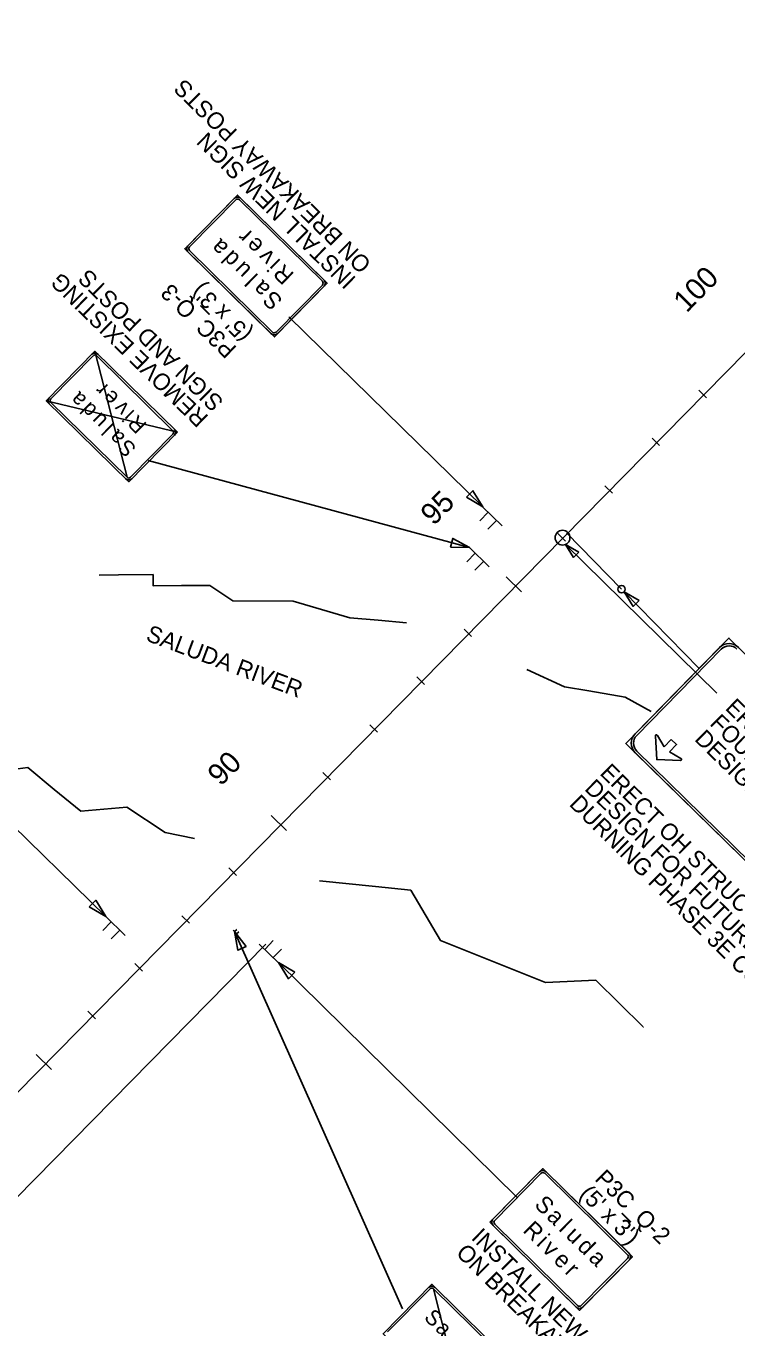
# Model space of a CAD drawing. Extents: x -5665 to 1997148, y 4 to 812485.
# Drawn here: x 1960598 to 1961659, y 796785 to 798728 of the extents above; entities that cross this region are included whole.
import ezdxf

# ---------------------------------------------------------------- set-up
doc = ezdxf.new("R2010")
doc.units = 0
for name, color, linetype in [('Default', 7, 'Continuous'), ('RD_HC_CL_Rel', 7, 'Continuous'), ('RD_HC_Data_Tic_Rel', 7, 'Continuous'), ('RD_HC_TX_Rel_Sta50', 7, 'Continuous'), ('RD_PD_Final_TX', 7, 'Continuous'), ('RD_SHT_ID', 7, 'Continuous'), ('RD_SHT_TX', 7, 'Continuous'), ('TR SN EXTRUDED PANEL SIGNS- MOUNTED OVERHEAD', 7, 'Continuous'), ('TR SN UNASSIGNED 10', 7, 'Continuous')]:
    doc.layers.add(name, color=color, linetype=linetype)

msp = doc.modelspace()

# ---------------------------------------------------------------- linework, layer by layer
at = {"layer": 'Default'}
msp.add_line((1960426.3, 796819.7), (1960955.8, 797357.9), dxfattribs=at)
at = {"layer": 'RD_HC_CL_Rel'}
msp.add_line((1957622, 794124.4), (1963740.1, 800343.8), dxfattribs=at)
at = {"layer": 'RD_HC_Data_Tic_Rel'}
for p, q in [((1961613.4, 798173.3), (1961602, 798184.6)), ((1961543.3, 798102), (1961531.9, 798113.3)), ((1961473.2, 798030.8), (1961461.7, 798042)), ((1961403, 797959.5), (1961391.6, 797970.7)), ((1961337.2, 797884), (1961314.4, 797906.4)), ((1961262.8, 797816.9), (1961251.4, 797828.1)), ((1961192.6, 797745.6), (1961181.2, 797756.8)), ((1961122.5, 797674.3), (1961111.1, 797685.5)), ((1961052.4, 797603), (1961041, 797614.2)), ((1960986.5, 797527.5), (1960963.7, 797550)), ((1960912.1, 797460.4), (1960900.7, 797471.7)), ((1960842, 797389.2), (1960830.6, 797400.4)), ((1960771.9, 797317.9), (1960760.5, 797329.1)), ((1960701.8, 797246.6), (1960690.3, 797257.8)), ((1960635.9, 797171.1), (1960613.1, 797193.5))]:
    msp.add_line(p, q, dxfattribs=at)
at = {"layer": 'RD_PD_Final_TX'}
for points in [[(1961255, 798024.9), (1961264.6, 798034.7), (1961279.5, 798010.4)], [(1961231, 797950.4), (1961234.6, 797963.6), (1961259.4, 797949.8)], [(1961422.6, 797943), (1961414.9, 797935.2), (1961403, 797954.6)], [(1960692.3, 797413.8), (1960701.9, 797423.6), (1960716.8, 797399.4)], [(1960926.6, 797354.6), (1960914.1, 797349), (1960909.2, 797377)], [(1960999.1, 797316.1), (1960989.4, 797306.3), (1960974.6, 797330.5)]]:
    msp.add_lwpolyline(points, close=True, dxfattribs=at)
at = {"layer": 'RD_SHT_ID'}
for points in [[(1961165.7, 797837.4), (1961123.4, 797841.3), (1961081.1, 797845.2), (1960996.3, 797869.9), (1960906.4, 797870.3), (1960872.3, 797893.3), (1960830, 797893), (1960787.7, 797892.6), (1960787.6, 797909.5), (1960735.8, 797909.1), (1960707.2, 797908.9)], [(1961345.1, 797768), (1961401.3, 797742), (1961401.3, 797742), (1961437.4, 797736), (1961492, 797726.8), (1961530.7, 797705)], [(1960849.1, 797515.5), (1960805.7, 797524.7), (1960748.2, 797562.3), (1960748.2, 797562.3), (1960679.5, 797556.5), (1960640.1, 797589), (1960600.7, 797621.5), (1960555.3, 797615.8), (1960534.7, 797613.2), (1960515.9, 797641.9), (1960503.2, 797633.6), (1960494.9, 797646.3), (1960494.9, 797646.3)], [(1961035.8, 797452.7), (1961119.1, 797444.1), (1961172, 797438.7), (1961216.1, 797363.5), (1961347.9, 797310.8), (1961373, 797300.8), (1961447.9, 797304.2), (1961483.4, 797269.4), (1961518.8, 797234.5), (1961518.8, 797234.5), (1961518.8, 797234.5)]]:
    msp.add_lwpolyline(points, dxfattribs=at)
at = {"layer": 'TR SN EXTRUDED PANEL SIGNS- MOUNTED OVERHEAD'}
for p, q in [((1960990, 798294.4), (1961279.5, 798010.4)), ((1960700.8, 798242.8), (1960748.6, 798054.7)), ((1960628.2, 798169), (1960823.8, 798121.9)), ((1960780.2, 798079.9), (1961259.4, 797949.8)), ((1961274.9, 797989.8), (1961287.2, 798002.6)), ((1961308.2, 797982.3), (1961278.7, 798010.9)), ((1961287.1, 797977.1), (1961299.5, 797989.9)), ((1961288.9, 797921.2), (1961259.4, 797949.8)), ((1961403, 797954.6), (1961628.8, 797732.5)), ((1961255.5, 797928.7), (1961267.9, 797941.5)), ((1961267.7, 797916), (1961280.1, 797928.8)), ((1960716.8, 797399.4), (1960410.5, 797698.9)), ((1960746, 797371.1), (1960716.5, 797399.6)), ((1960712.7, 797378.5), (1960725, 797391.3)), ((1960724.9, 797365.8), (1960737.3, 797378.6)), ((1960907, 797378.7), (1960914.1, 797371.3)), ((1960912.4, 797379.8), (1960909.2, 797376.7)), ((1961159.6, 796813.7), (1960909.2, 797377)), ((1960915.3, 797376.5), (1960912.1, 797373.4)), ((1960966.9, 797363.4), (1960954.5, 797350.6)), ((1960945.7, 797358.2), (1960975.3, 797329.7)), ((1960979.1, 797350.7), (1960966.7, 797337.9)), ((1960974.6, 797330.5), (1961330.9, 796980)), ((1961253.7, 796655.6), (1961205.9, 796843.8))]:
    msp.add_line(p, q, dxfattribs=at)
for points in [[(1961047.3, 798344.5), (1960913.6, 798476), (1960834.7, 798395.8), (1960968.4, 798264.3), (1961047.3, 798344.5), (1961047.3, 798344.5), (1961047.3, 798344.5)], [(1960839.7, 798400.8), (1960908.7, 798471)], [(1960910.9, 798468.8), (1960841.9, 798398.6)], [(1960910.9, 798468.8), (1960910.9, 798468.8), (1960910.9, 798468.8)], [(1961040.1, 798347.2), (1960916.4, 798468.8)], [(1960918.6, 798471), (1961042.3, 798349.4)], [(1960963.4, 798269.2), (1960839.7, 798390.8)], [(1960841.9, 798393.1), (1960965.6, 798271.4)], [(1960841.9, 798393.1), (1960841.9, 798393.1), (1960841.9, 798393.1)], [(1960971.1, 798271.5), (1961040.1, 798341.7)], [(1961042.4, 798339.5), (1960973.3, 798269.3)], [(1961040.1, 798347.2), (1961040.1, 798347.2), (1961040.1, 798347.2)], [(1960971.1, 798271.5), (1960971.1, 798271.5), (1960971.1, 798271.5)], [(1960823.8, 798121.9), (1960700.8, 798242.8), (1960628.2, 798169), (1960751.2, 798048.1), (1960823.8, 798121.9), (1960823.8, 798121.9), (1960823.8, 798121.9)], [(1960698.3, 798236.2), (1960634.8, 798171.6)], [(1960698.3, 798236.2), (1960698.3, 798236.2), (1960698.3, 798236.2)], [(1960817.1, 798124.3), (1960703.4, 798236.2)], [(1960634.8, 798166.6), (1960748.6, 798054.7)], [(1960634.8, 798166.6), (1960634.8, 798166.6), (1960634.8, 798166.6)], [(1960753.7, 798054.7), (1960817.2, 798119.3)], [(1960817.1, 798124.3), (1960817.1, 798124.3), (1960817.1, 798124.3)], [(1960753.7, 798054.7), (1960753.7, 798054.7), (1960753.7, 798054.7)], [(1961290.1, 796942.9), (1961423.7, 796811.4), (1961502.6, 796891.6), (1961368.9, 797023.1), (1961290.1, 796942.9), (1961290.1, 796942.9), (1961290.1, 796942.9)], [(1961295, 796947.9), (1961364, 797018.1)], [(1961366.2, 797015.9), (1961297.2, 796945.8)], [(1961366.2, 797015.9), (1961366.2, 797015.9), (1961366.2, 797015.9)], [(1961495.4, 796894.3), (1961371.8, 797016)], [(1961374, 797018.2), (1961497.6, 796896.6)], [(1961418.7, 796816.4), (1961295.1, 796938)], [(1961297.3, 796940.2), (1961420.9, 796818.6)], [(1961297.3, 796940.2), (1961297.3, 796940.2), (1961297.3, 796940.2)], [(1961495.4, 796894.3), (1961495.4, 796894.3), (1961495.4, 796894.3)], [(1961426.4, 796818.6), (1961495.5, 796888.8)], [(1961497.7, 796886.6), (1961428.7, 796816.5)], [(1961130.7, 796776.6), (1961253.7, 796655.6), (1961326.3, 796729.4), (1961203.3, 796850.4), (1961130.7, 796776.6), (1961130.7, 796776.6), (1961130.7, 796776.6)], [(1961200.8, 796843.8), (1961137.3, 796779.2)], [(1961200.8, 796843.8), (1961200.8, 796843.8), (1961200.8, 796843.8)], [(1961319.6, 796731.9), (1961205.9, 796843.8)], [(1961426.4, 796818.6), (1961426.4, 796818.6), (1961426.4, 796818.6)]]:
    msp.add_lwpolyline(points, dxfattribs=at)
msp.add_circle((1961398.4, 797964.7), 11.1, dxfattribs=at)
for centre, radius, start, end in [((1960913.7, 798466), 7.03, 45.4705, 135.4707), ((1960913.7, 798466), 3.91, 45.4705, 135.4707), ((1960844.7, 798395.9), 7.03, 135.4705, 225.4707), ((1960844.7, 798395.9), 3.91, 135.4705, 225.4707), ((1961037.3, 798344.4), 3.91, 315.4703, 45.4705), ((1961037.3, 798344.4), 7.03, 315.4703, 45.4705), ((1960968.3, 798274.2), 7.03, 225.4707, 315.4703), ((1960968.3, 798274.2), 3.91, 225.4707, 315.4703), ((1960700.9, 798233.7), 6.47, 45.4705, 135.4707), ((1960700.9, 798233.7), 3.59, 45.4705, 135.4707), ((1960637.4, 798169.1), 6.47, 135.4705, 225.4707), ((1960637.4, 798169.1), 3.59, 135.4705, 225.4707), ((1960814.6, 798121.8), 3.59, 315.4703, 45.4705), ((1960814.6, 798121.8), 6.47, 315.4703, 45.4705), ((1960751.1, 798057.2), 6.47, 225.4707, 315.4703), ((1960751.1, 798057.2), 3.59, 225.4707, 315.4703), ((1961369, 797013.2), 7.03, 45.4707, 135.4703), ((1961369, 797013.2), 3.91, 45.4707, 135.4703), ((1961300, 796943), 7.03, 135.4703, 225.4705), ((1961300, 796943), 3.91, 135.4703, 225.4705), ((1961492.7, 796891.6), 3.91, 315.4705, 45.4707), ((1961492.7, 796891.6), 7.03, 315.4705, 45.4707), ((1961203.4, 796841.2), 6.47, 45.4707, 135.4703), ((1961203.4, 796841.2), 3.59, 45.4707, 135.4703), ((1961423.6, 796821.4), 3.91, 225.4705, 315.4707), ((1961423.6, 796821.4), 7.03, 225.4705, 315.4707)]:
    msp.add_arc(centre, radius, start, end, dxfattribs=at)
at = {"layer": 'TR SN UNASSIGNED 10'}
for p, q in [((1961404.4, 797971.8), (1961486.5, 797887.8)), ((1961602.2, 797769.4), (1961490.5, 797883.9)), ((1961536.9, 797668.6), (1961538.9, 797633.4)), ((1961550.2, 797652.6), (1961540, 797669.6)), ((1961560.7, 797663.3), (1961550.2, 797652.6)), ((1961538.9, 797633.4), (1961574.2, 797632.1)), ((1961575.1, 797635.2), (1961558, 797645))]:
    msp.add_line(p, q, dxfattribs=at)
msp.add_lwpolyline([(1961512.5, 797870.9), (1961503.8, 797862.1), (1961490.5, 797883.9)], close=True, dxfattribs=at)
for points in [[(1961492.7, 797657.6), (1961907, 797251.7), (1962061, 797408.8), (1961646.7, 797814.8), (1961492.7, 797657.6), (1961492.7, 797657.6)], [(1961506.7, 797671.9), (1961632.7, 797800.5)], [(1961635.1, 797798.2), (1961509.1, 797669.6)], [(1961536.9, 797668.6), (1961538.9, 797633.4), (1961538.9, 797633.4)], [(1961550.2, 797652.6), (1961540, 797669.6)], [(1961550.2, 797652.6), (1961560.7, 797663.3), (1961560.7, 797663.3)], [(1961560.7, 797663.3), (1961568.5, 797655.8), (1961558, 797645)], [(1961558, 797645), (1961568.5, 797655.8), (1961560.7, 797663.3)], [(1961892.7, 797265.7), (1961507, 797643.6)], [(1961509.3, 797646), (1961895, 797268.1)], [(1961538.9, 797633.4), (1961574.2, 797632.1)], [(1961575.1, 797635.2), (1961558, 797645)]]:
    msp.add_lwpolyline(points, dxfattribs=at)
msp.add_circle((1961486.5, 797887.8), 5.54, dxfattribs=at)
for centre, radius, start, end in [((1961647, 797786.5), 20, 45.5831, 135.5828), ((1961647, 797786.5), 16.7, 45.5831, 135.5828), ((1961521, 797657.9), 20, 135.5828, 225.583), ((1961521, 797657.9), 16.7, 135.5828, 225.583), ((1961538.6, 797668.7), 1.67, 31.1102, 182.5579), ((1961538.6, 797668.7), 1.67, 31.1102, 182.5579), ((1961574.3, 797633.7), 1.67, 268.6081, 60.0557), ((1961574.3, 797633.7), 1.67, 268.6081, 60.0557)]:
    msp.add_arc(centre, radius, start, end, dxfattribs=at)

# ---------------------------------------------------------------- texts
at = {"layer": 'RD_HC_TX_Rel_Sta50'}
for s, p in [('100', (1961583.5, 798299.2)), ('95', (1961206.2, 797981.4)), ('90', (1960888.4, 797592.6))]:
    msp.add_text(s, height=32, rotation=45.4705, dxfattribs=at).set_placement(p)
at = {"layer": 'RD_SHT_TX'}
msp.add_text('SALUDA RIVER', height=25, rotation=339.371, dxfattribs=at).set_placement((1960775.2, 797811.6))
at = {"layer": 'TR SN EXTRUDED PANEL SIGNS- MOUNTED OVERHEAD'}
for s, height, rotation, p in [('ON BREAKAWAY POSTS', 25, 135.4705, (1961114.6, 798374.6)), ('INSTALL NEW SIGN', 25, 135.4705, (1961091.8, 798351.4)), ('a', 25, 135.4705, (1960901.3, 798399.3)), ('r', 25, 135.4705, (1960936.5, 798419.5)), ('e', 25, 135.4705, (1960953.7, 798402.6)), ('d', 25, 135.4705, (1960918.4, 798382.5)), ('v', 25, 135.4705, (1960970.7, 798385.9)), ('u', 25, 135.4705, (1960935.4, 798365.8)), ('i', 25, 135.4705, (1960979, 798377.7)), ('R', 25, 135.4705, (1960999.2, 798357.8)), ('REMOVE EXISTING', 25, 135.6376, (1960871.5, 798145.2)), ('SIGN AND POSTS', 25, 135.6376, (1960894.2, 798168.5)), ('l', 25, 135.4705, (1960945.6, 798355.7)), ('P3C_Q-3', 25, 135.6376, (1960913.8, 798248.1)), ("(5' x 3')", 25, 135.6376, (1960936.6, 798271.3)), ('a', 25, 135.4705, (1960963.9, 798337.7)), ('S', 25, 135.4705, (1960982.3, 798319.6)), ('a', 23, 135.4705, (1960689.5, 798172.3)), ('r', 23, 135.4705, (1960721.9, 798190.8)), ('e', 23, 135.4705, (1960737.7, 798175.3)), ('d', 23, 135.4705, (1960705.2, 798156.9)), ('v', 23, 135.4705, (1960753.3, 798160)), ('u', 23, 135.4705, (1960720.8, 798141.4)), ('i', 23, 135.4705, (1960761, 798152.4)), ('R', 23, 135.4705, (1960779.5, 798134.1)), ('l', 23, 135.4705, (1960730.2, 798132.2)), ('a', 23, 135.4705, (1960747.1, 798115.6)), ('S', 23, 135.4705, (1960764, 798099)), ('ERECT OVERHEAD BRIDGE TYPE STRUCTURE', 25, 315.4705, (1961639.7, 797709.1)), ('FOUNDATION NO. P3C_OH-9 IN MEDIAN ONLY.', 25, 315.4705, (1961616.9, 797685.9)), ("DESIGN FUTURE BRIDGE STRUCTURE FOR SIGN SIZE 70'x 18'.", 25, 315.4705, (1961594, 797662.7)), ('P3C_Q-2', 25, 315.3323, (1961445.1, 797006.3)), ("(5' x 3')", 25, 315.3323, (1961422.2, 796983.1)), ('S', 25, 315.4705, (1961355, 796967.8)), ('a', 25, 315.4705, (1961373.4, 796949.7)), ('INSTALL NEW SIGN', 25, 315.4705, (1961260.9, 796918.7)), ('R', 25, 315.4705, (1961338.1, 796929.6)), ('l', 25, 315.4705, (1961391.7, 796931.7)), ('u', 25, 315.4705, (1961401.9, 796921.7)), ('i', 25, 315.4705, (1961358.3, 796909.8)), ('v', 25, 315.4705, (1961366.7, 796901.5)), ('d', 25, 315.4705, (1961419, 796904.9)), ('ON BREAKAWAY POSTS', 25, 315.4705, (1961238, 796895.5)), ('e', 25, 315.4705, (1961383.6, 796884.8)), ('a', 25, 315.4705, (1961436, 796888.1)), ('r', 25, 315.4705, (1961400.8, 796867.9)), ('S', 23, 315.4705, (1961190.5, 796799.4)), ('a', 23, 315.4705, (1961207.4, 796782.8))]:
    msp.add_text(s, height=height, rotation=rotation, dxfattribs=at).set_placement(p)
at = {"layer": 'TR SN UNASSIGNED 10'}
for s, p in [('ERECT OH STRUCTURE NO. 37.', (1961452.7, 797612)), ('DESIGN FOR FUTURE SIGNS  TO BE ADDED', (1961429.9, 797588.8)), ('DURNING PHASE 3E CONSTRUCTION.', (1961407, 797565.7))]:
    msp.add_text(s, height=25, rotation=315.3323, dxfattribs=at).set_placement(p)

doc.saveas('drawing.dxf')
